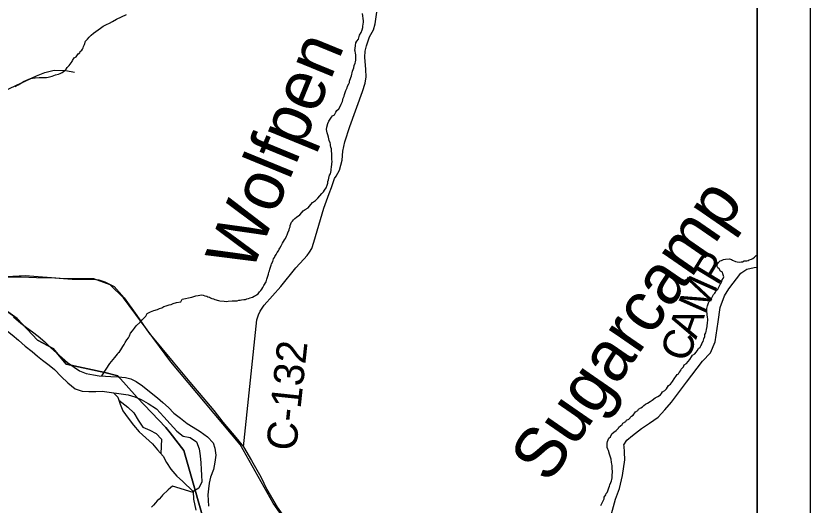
# Model space of a CAD drawing. Extents: x 44.2 to 78.2, y 4.5 to 26.5.
# Drawn here: x 51.74 to 53.236, y 19.485 to 20.407 of the extents above; entities that cross this region are included whole.
import ezdxf

# ---------------------------------------------------------------- set-up
doc = ezdxf.new("R2010")
doc.units = 0
for name, color, linetype in [('GM_X_County_Road', 7, 'Continuous'), ('GM_X_County_Road_Text', 7, 'Continuous'), ('GM_X_Major_River', 7, 'Continuous'), ('GM_X_Minor_River', 7, 'Continuous'), ('GM_X_Minor_River_Text', 7, 'Continuous'), ('GM_X_Rail_Line', 7, 'Continuous'), ('GM_X_Township_Road', 7, 'Continuous'), ('GM_X_Township_Road_Text', 7, 'Continuous'), ('GM_X_US_Route', 7, 'Continuous'), ('SH_Cut_Line', 7, 'Continuous'), ('SH_Data', 7, 'Continuous')]:
    doc.layers.add(name, color=color, linetype=linetype)

msp = doc.modelspace()

# ---------------------------------------------------------------- linework, layer by layer
at = {"layer": 'GM_X_County_Road'}
msp.add_lwpolyline([(52.1689, 19.5951), (52.1943, 19.834), (52.1973, 19.8438), (52.2001, 19.8505), (52.208, 19.8617), (52.2391, 19.8967), (52.2676, 19.9319), (52.2827, 19.9482), (52.2887, 19.9556), (52.2931, 19.9616), (52.2978, 19.9688), (52.3017, 19.9807), (52.32, 20.0445), (52.3251, 20.0581), (52.3305, 20.0721), (52.3349, 20.0834), (52.3406, 20.1002), (52.3434, 20.105), (52.3497, 20.1161), (52.3548, 20.1352), (52.3562, 20.1523), (52.3597, 20.1697), (52.3692, 20.1983), (52.3932, 20.2645), (52.3978, 20.2803), (52.3998, 20.2919), (52.3992, 20.3061), (52.3976, 20.329), (52.3982, 20.3404), (52.4007, 20.3506), (52.4064, 20.3671), (52.4136, 20.3809), (52.4171, 20.3916), (52.4198, 20.4137)], dxfattribs=at)
at = {"layer": 'GM_X_Major_River'}
for points in [[(51.6471, 19.8674), (51.6715, 19.8465), (51.6837, 19.8402), (51.695, 19.8327), (51.7082, 19.8261), (51.7213, 19.8156), (51.7336, 19.8059), (51.7451, 19.7958), (51.7582, 19.7846), (51.7713, 19.7745), (51.781, 19.766), (51.7907, 19.7582), (51.803, 19.7485), (51.8131, 19.7404), (51.8257, 19.7276), (51.8384, 19.7153), (51.8518, 19.7044), (51.8654, 19.6996), (51.8779, 19.6991), (51.8907, 19.6992), (51.9029, 19.6998)], [(51.7361, 19.8401), (51.7495, 19.8281), (51.7603, 19.8199), (51.7716, 19.8118), (51.7824, 19.8032), (51.7951, 19.7928), (51.8055, 19.7823), (51.8174, 19.7715), (51.8275, 19.7626), (51.8379, 19.7537), (51.8503, 19.7448), (51.8604, 19.7381), (51.8728, 19.733), (51.8864, 19.7305), (51.8973, 19.7288), (51.9094, 19.7279), (51.9193, 19.7277), (51.9329, 19.7267), (51.9469, 19.7258), (51.9567, 19.7233), (51.9672, 19.7178), (51.9788, 19.7097), (51.9949, 19.6965), (52.0068, 19.6872), (52.0173, 19.6786), (52.0277, 19.669), (52.0377, 19.6585), (52.0501, 19.6488), (52.0631, 19.6391), (52.074, 19.6317), (52.0871, 19.6239), (52.1013, 19.6138), (52.1117, 19.6022), (52.1149, 19.5927), (52.1166, 19.5789), (52.1152, 19.5657), (52.1123, 19.5524), (52.1068, 19.538), (52.1043, 19.5266), (52.103, 19.5156), (52.102, 19.5042), (52.1022, 19.4947), (52.1028, 19.4829)], [(51.9029, 19.6998), (51.9516, 19.693), (51.9644, 19.689), (51.9761, 19.6838), (51.9892, 19.6764), (52.0053, 19.6663), (52.0187, 19.6512), (52.0309, 19.6381), (52.0432, 19.6246), (52.0555, 19.6153), (52.0687, 19.6124), (52.0803, 19.6042), (52.0858, 19.5912), (52.0874, 19.5779), (52.0887, 19.5645), (52.0892, 19.552), (52.0898, 19.5413), (52.0903, 19.5288), (52.0852, 19.517), (52.0745, 19.5107), (52.0746, 19.4963), (52.0795, 19.4757)]]:
    msp.add_lwpolyline(points, dxfattribs=at)
at = {"layer": 'GM_X_Minor_River'}
for points in [[(51.7392, 20.2739), (51.745, 20.2772), (51.7511, 20.2808), (51.7558, 20.2837), (51.7592, 20.2852), (51.7646, 20.2877), (51.7677, 20.2887), (51.7715, 20.2898), (51.7768, 20.29), (51.7844, 20.291), (51.7947, 20.2907), (51.7981, 20.291), (51.8015, 20.2913), (51.8088, 20.2934), (51.8149, 20.2955), (51.8207, 20.2968), (51.8241, 20.2986), (51.8276, 20.3001), (51.8299, 20.3019), (51.8326, 20.3041), (51.835, 20.3067), (51.8373, 20.3097), (51.8405, 20.3134), (51.8448, 20.3186), (51.8467, 20.3208), (51.8472, 20.3231), (51.8503, 20.3276), (51.8538, 20.3297), (51.8577, 20.3353), (51.8608, 20.3375), (51.8616, 20.3398), (51.8647, 20.342), (51.8659, 20.3442), (51.8671, 20.3468), (51.8676, 20.3495), (51.8696, 20.3532), (51.8716, 20.3592), (51.8751, 20.3629), (51.8783, 20.367), (51.8822, 20.3707), (51.8868, 20.3744), (51.8911, 20.3773), (51.8953, 20.3806), (51.8996, 20.3836), (51.9046, 20.3872), (51.9112, 20.3905), (51.9166, 20.3934), (51.9223, 20.3966), (51.93, 20.4006), (51.9485, 20.4092)], [(52.3938, 20.3877), (52.3948, 20.3953), (52.3949, 20.3975), (52.3942, 20.4017), (52.3936, 20.4067), (52.3929, 20.4112)], [(52.2497, 19.9916), (52.2513, 19.9946), (52.2525, 19.9979), (52.255, 20.004), (52.2558, 20.007), (52.2566, 20.0096), (52.2571, 20.0119), (52.2595, 20.0179), (52.2611, 20.0201), (52.263, 20.0227), (52.2654, 20.0253), (52.2689, 20.0279), (52.275, 20.0319), (52.2786, 20.0363), (52.2813, 20.0397), (52.2852, 20.0422), (52.291, 20.0455), (52.2957, 20.0518), (52.2988, 20.0552), (52.3046, 20.0592), (52.3089, 20.0632), (52.3128, 20.0681), (52.3167, 20.0722), (52.3198, 20.0751), (52.3218, 20.0785), (52.3246, 20.0826), (52.3266, 20.0882), (52.3275, 20.092), (52.3279, 20.095), (52.3291, 20.098), (52.3296, 20.101), (52.3312, 20.1067), (52.3325, 20.1093), (52.3338, 20.1157), (52.3342, 20.1187), (52.3347, 20.1214), (52.3352, 20.1282), (52.3357, 20.1327), (52.3354, 20.1362), (52.3356, 20.1441), (52.3353, 20.1472), (52.3347, 20.1525), (52.3344, 20.1563), (52.3337, 20.1597), (52.333, 20.1624), (52.3327, 20.1651), (52.332, 20.1677), (52.3306, 20.1719), (52.3299, 20.175), (52.3289, 20.1784), (52.3279, 20.1826), (52.3264, 20.1865), (52.3258, 20.1895), (52.3255, 20.1926), (52.326, 20.1975), (52.3276, 20.2039), (52.3297, 20.2088), (52.332, 20.2121), (52.3348, 20.2162), (52.3368, 20.2185), (52.3402, 20.2206), (52.343, 20.2255), (52.345, 20.2285), (52.3485, 20.2318), (52.3513, 20.2363), (52.3529, 20.2408), (52.3553, 20.2453), (52.3561, 20.2487), (52.3566, 20.2517), (52.3586, 20.2554), (52.359, 20.2585), (52.3615, 20.2664), (52.3643, 20.2716), (52.3651, 20.2742), (52.3671, 20.2787), (52.3684, 20.2814), (52.3688, 20.2836), (52.3709, 20.2908), (52.3725, 20.2942), (52.3742, 20.3025), (52.3767, 20.3089), (52.3771, 20.3134), (52.3792, 20.3179), (52.38, 20.3205), (52.3804, 20.3235), (52.3806, 20.3308), (52.3803, 20.3334), (52.38, 20.3365), (52.379, 20.3403), (52.3786, 20.3426), (52.3791, 20.3452), (52.3796, 20.3513), (52.3805, 20.3562), (52.3825, 20.3595), (52.3853, 20.3633), (52.3869, 20.3678), (52.3877, 20.3704), (52.3905, 20.3753), (52.3922, 20.3809), (52.3938, 20.3847), (52.3938, 20.3877)], [(51.9021, 19.7284), (51.9173, 19.7518), (51.9267, 19.7633), (51.9318, 19.7696), (51.933, 19.7718), (51.9354, 19.7737), (51.9378, 19.7778), (51.9397, 19.7808), (51.9421, 19.7841), (51.9441, 19.7875), (51.9464, 19.7912), (51.9496, 19.7968), (51.9524, 19.8005), (51.9544, 19.8039), (51.9564, 19.8088), (51.9599, 19.8136), (51.9619, 19.8158), (51.9635, 19.8185), (51.9666, 19.8229), (51.9744, 19.8296), (51.9779, 19.834), (51.9853, 19.841), (51.9877, 19.8459), (51.9939, 19.8495), (52, 19.8517), (52.0073, 19.8534), (52.0111, 19.8555), (52.015, 19.8566), (52.0188, 19.8591), (52.0234, 19.8605), (52.0288, 19.8623), (52.0326, 19.8633), (52.0364, 19.8647), (52.0426, 19.8669), (52.0513, 19.8681), (52.0534, 19.873), (52.0717, 19.8767), (52.0793, 19.8792), (52.0839, 19.8802), (52.0866, 19.8809), (52.0896, 19.8812), (52.0931, 19.8807), (52.0964, 19.8795), (52.0998, 19.8786), (52.1021, 19.8778), (52.1047, 19.877), (52.107, 19.8758), (52.1096, 19.8746), (52.1122, 19.8738), (52.1152, 19.8722), (52.1217, 19.8705), (52.1247, 19.87), (52.1323, 19.8691), (52.1368, 19.8689), (52.1402, 19.8692), (52.1475, 19.8698), (52.1539, 19.87), (52.157, 19.8703), (52.16, 19.871), (52.1627, 19.8713), (52.165, 19.8716), (52.1699, 19.8722), (52.1726, 19.8726), (52.1753, 19.8736), (52.1784, 19.8743), (52.1818, 19.8757), (52.186, 19.8771), (52.1891, 19.879), (52.1914, 19.88), (52.1937, 19.8815), (52.1964, 19.8829), (52.1992, 19.8867), (52.2015, 19.8893), (52.2035, 19.8919), (52.2055, 19.8952), (52.2075, 19.8986), (52.2114, 19.9061), (52.2131, 19.9106), (52.2143, 19.9143), (52.216, 19.9204), (52.2168, 19.9238), (52.2177, 19.9264), (52.2185, 19.9298), (52.2197, 19.9335), (52.221, 19.9369), (52.2218, 19.9396), (52.2242, 19.9444), (52.225, 19.9467), (52.2254, 19.949), (52.2274, 19.9516), (52.2279, 19.9538), (52.2302, 19.9576), (52.2322, 19.9613), (52.2346, 19.9643), (52.2362, 19.9673), (52.2377, 19.9695), (52.2401, 19.9736), (52.2425, 19.9789), (52.2465, 19.9848), (52.2481, 19.9874), (52.2497, 19.9916)], [(52.9691, 19.7102), (52.973, 19.7128), (52.9746, 19.7157), (52.9769, 19.718), (52.9801, 19.7232), (52.9841, 19.7292), (52.9856, 19.7314), (52.9883, 19.7325), (52.9895, 19.7347), (52.9923, 19.7388), (52.9931, 19.7411), (52.9974, 19.7459), (52.9986, 19.7493), (53.0033, 19.7522), (53.006, 19.7555), (53.0091, 19.7596), (53.0127, 19.7645), (53.0143, 19.7674), (53.0185, 19.77), (53.0213, 19.7733), (53.0232, 19.7759), (53.026, 19.7804), (53.0287, 19.7826), (53.0299, 19.7849), (53.0315, 19.7871), (53.0327, 19.7909), (53.0343, 19.7931), (53.0359, 19.7984), (53.0376, 19.8025), (53.0377, 19.8067), (53.0393, 19.81), (53.0401, 19.8123), (53.0406, 19.8157), (53.0419, 19.8217), (53.0423, 19.8244), (53.0428, 19.8274), (53.043, 19.835), (53.0427, 19.8396), (53.042, 19.843), (53.0421, 19.8453), (53.0414, 19.8498), (53.0416, 19.8555), (53.042, 19.8582), (53.0425, 19.8604), (53.0433, 19.8627), (53.0445, 19.8664), (53.0457, 19.8687), (53.0484, 19.8713), (53.0504, 19.8746), (53.052, 19.878), (53.054, 19.8821), (53.0564, 19.8843), (53.0579, 19.8866), (53.0595, 19.8899), (53.0619, 19.8922), (53.0642, 19.8955), (53.0671, 19.9023), (53.0698, 19.9064), (53.0703, 19.9098), (53.0723, 19.912), (53.0731, 19.915), (53.0717, 19.9207), (53.0707, 19.9242), (53.0673, 19.9262), (53.0644, 19.93), (53.0618, 19.9324), (53.0607, 19.9347), (53.0608, 19.9385), (53.0635, 19.9422), (53.0666, 19.9452), (53.069, 19.9462), (53.0728, 19.9477), (53.0766, 19.9487), (53.0838, 19.9489), (53.0876, 19.9476), (53.0899, 19.9468), (53.0951, 19.9444), (53.0985, 19.9432), (53.1031, 19.9431), (53.1061, 19.9434), (53.1088, 19.9437), (53.1118, 19.9451), (53.1141, 19.9451), (53.1164, 19.9454), (53.1191, 19.9461), (53.1214, 19.9471), (53.1256, 19.9482), (53.1279, 19.95), (53.131, 19.9522), (53.1345, 19.9551), (53.1359, 19.9558)], [(52.8415, 19.4844), (52.843, 19.4866), (52.8459, 19.493), (52.8479, 19.4967), (52.8483, 19.5001), (52.8515, 19.5042), (52.8519, 19.5069), (52.8539, 19.5091), (52.8551, 19.5117), (52.8567, 19.5174), (52.8584, 19.5207), (52.8588, 19.5234), (52.8608, 19.5275), (52.862, 19.5309), (52.8625, 19.5332), (52.8629, 19.5366), (52.8634, 19.5407), (52.8636, 19.5479), (52.8634, 19.5544), (52.8631, 19.5589), (52.8625, 19.5627), (52.8621, 19.5654), (52.8615, 19.5715), (52.8601, 19.5757), (52.858, 19.5811), (52.8563, 19.5879), (52.8552, 19.5903), (52.8538, 19.5937), (52.8535, 19.599), (52.8536, 19.6017), (52.8544, 19.6047), (52.8569, 19.6111), (52.8603, 19.6136), (52.8628, 19.6193), (52.8663, 19.6226), (52.8709, 19.6255), (52.8748, 19.63), (52.876, 19.6322), (52.8818, 19.637), (52.8834, 19.6392), (52.8888, 19.6425), (52.8904, 19.6451), (52.8946, 19.6473), (52.8993, 19.6528), (52.9024, 19.6547), (52.9071, 19.6606), (52.9117, 19.6635), (52.9129, 19.6661), (52.9172, 19.6683), (52.9203, 19.6705), (52.9226, 19.6727), (52.9261, 19.6753), (52.9296, 19.6771), (52.9346, 19.6804), (52.9384, 19.6829), (52.9439, 19.6873), (52.9492, 19.6895), (52.9539, 19.6928), (52.9562, 19.6957), (52.9578, 19.6984), (52.9621, 19.7009), (52.9652, 19.7042), (52.9691, 19.7102)], [(51.924, 19.6968), (51.9326, 19.6887), (51.9365, 19.6753), (51.942, 19.6627), (51.9516, 19.6492), (51.9619, 19.6357), (51.9727, 19.6234), (51.985, 19.6118), (51.9977, 19.6006), (52.0069, 19.5894), (52.0177, 19.5774), (52.0243, 19.5652), (52.0324, 19.5529), (52.0432, 19.5398), (52.0544, 19.5301), (52.0745, 19.5107)], [(51.9343, 19.6829), (51.9512, 19.6698), (51.9627, 19.6589), (51.9704, 19.6451), (51.9793, 19.6317), (51.9928, 19.6261), (52.0048, 19.6202), (52.0145, 19.6091), (52.0133, 19.5824)], [(52.0745, 19.509), (52.0353, 19.5206), (52.0318, 19.5177), (52.0271, 19.514), (52.0162, 19.5037), (52.0143, 19.5011), (52.01, 19.4966), (52.0065, 19.4929), (52.0033, 19.4892), (51.9994, 19.4852), (51.9959, 19.4811)]]:
    msp.add_lwpolyline(points, dxfattribs=at)
at = {"layer": 'GM_X_Rail_Line'}
for points in [[(53.1359, 18.9756), (53.1359, 25.4014)], [(53.1359, 18.8803), (52.8787, 18.9518), (52.4529, 19.1732), (52.4355, 19.1892), (52.2249, 19.4887), (52.1626, 19.5993), (52.0324, 19.7548), (51.9429, 19.8757), (51.918, 19.9004), (51.8875, 19.9114), (51.8322, 19.9117), (51.7576, 19.9172), (51.6529, 19.9117)], [(51.7043, 19.8639), (51.7427, 19.8368), (51.7811, 19.7961), (51.8105, 19.7803), (51.8353, 19.7509), (51.9076, 19.7351), (51.9324, 19.7284), (51.9686, 19.6877), (52.0228, 19.6312), (52.0308, 19.6211), (52.0567, 19.5883), (52.1063, 19.4143)], [(52.1063, 19.4143), (52.0567, 19.5883), (52.0308, 19.6211), (52.0228, 19.6312), (51.9686, 19.6877), (51.9324, 19.7284), (51.9076, 19.7351), (51.8353, 19.7509), (51.8105, 19.7803), (51.7811, 19.7961), (51.7427, 19.8368), (51.7043, 19.8639)]]:
    msp.add_lwpolyline(points, dxfattribs=at)
at = {"layer": 'GM_X_Township_Road'}
for points in [[(51.3852, 20.0768), (51.3966, 20.0815), (51.4092, 20.0852), (51.4232, 20.0891), (51.4386, 20.0943), (51.4515, 20.1002), (51.4663, 20.1105), (51.4796, 20.1201), (51.4963, 20.1372), (51.5095, 20.1449), (51.5268, 20.1557), (51.5418, 20.1655), (51.5598, 20.1727), (51.576, 20.1795), (51.5991, 20.1911), (51.6257, 20.2149), (51.6425, 20.2251), (51.6701, 20.2428), (51.7791, 20.2941), (51.7952, 20.3005), (51.8123, 20.3043), (51.8346, 20.3038), (51.8508, 20.3011)], [(52.8855, 19.5964), (52.8854, 19.5984), (52.8909, 19.6072), (52.9015, 19.6161), (52.9181, 19.6294), (52.9335, 19.6392), (52.95, 19.6508), (52.9625, 19.6644), (52.975, 19.6789), (53.0029, 19.7165), (53.0334, 19.7562), (53.0485, 19.7721), (53.0571, 19.7925), (53.0628, 19.8306), (53.0668, 19.8576), (53.0745, 19.8791), (53.0829, 19.8923), (53.1054, 19.9224), (53.117, 19.9299), (53.1306, 19.9329), (53.1359, 19.9336)], [(52.6304, 19.0813), (52.6336, 19.0862), (52.6552, 19.1086), (52.7307, 19.1855), (52.7536, 19.2061), (52.783, 19.2436), (52.8004, 19.2699), (52.8199, 19.2941), (52.8353, 19.3196), (52.8358, 19.3203), (52.8498, 19.3476), (52.8557, 19.3693), (52.8525, 19.3988), (52.8491, 19.4228), (52.8695, 19.4965), (52.8768, 19.5163), (52.8829, 19.541), (52.8868, 19.5707), (52.8861, 19.5848), (52.8855, 19.5964)]]:
    msp.add_lwpolyline(points, dxfattribs=at)
at = {"layer": 'GM_X_US_Route'}
for points in [[(51.7255, 19.9152), (51.7501, 19.9154), (51.7793, 19.9142), (51.8137, 19.9133), (51.8466, 19.911), (51.8855, 19.911), (51.8969, 19.9097), (51.9079, 19.9059), (51.9153, 19.9023), (51.9252, 19.8967), (51.9446, 19.8758), (51.9681, 19.8421), (51.991, 19.8098), (52.0155, 19.7802), (52.0364, 19.7544), (52.0397, 19.7505)], [(52.0397, 19.7505), (52.068, 19.7167), (52.0922, 19.6876), (52.1129, 19.6632), (52.1302, 19.6415), (52.1513, 19.6165), (52.1689, 19.5951)], [(52.1689, 19.5951), (52.1843, 19.5689), (52.2016, 19.5381), (52.2128, 19.5146), (52.2321, 19.4812), (52.2495, 19.4575), (52.2541, 19.451)]]:
    msp.add_lwpolyline(points, dxfattribs=at)
at = {"layer": 'SH_Cut_Line'}
msp.add_lwpolyline([(48.642, 18.6014), (53.1359, 18.6014), (53.1359, 25.4014)], dxfattribs=at)
at = {"layer": 'SH_Data'}
for p, q in [((53.2359, 25.5014), (53.2359, 18.5014)), ((53.1359, 25.4014), (53.1359, 18.6014))]:
    msp.add_line(p, q, dxfattribs=at)

# ---------------------------------------------------------------- texts
at = {"layer": 'GM_X_County_Road_Text'}
msp.add_text('C-132', height=0.05682, rotation=83.9334, dxfattribs=at).set_placement((52.2679, 19.5858))
at = {"layer": 'GM_X_Minor_River_Text'}
for s, rotation, p in [('Wolfpen', 67.6865, (52.1831, 19.9198)), ('Sugarcamp', 55.343, (52.7437, 19.5234))]:
    msp.add_text(s, height=0.09471, rotation=rotation, dxfattribs=at).set_placement(p)
at = {"layer": 'GM_X_Township_Road_Text'}
for s, rotation, p in [('P', 58.7209, (53.0619, 19.8967)), ('M', 66.0393, (53.0377, 19.842)), ('A', 70.1492, (53.0211, 19.796)), ('C', 70.1863, (53.0053, 19.7521))]:
    msp.add_text(s, height=0.0568, rotation=rotation, dxfattribs=at).set_placement(p)

doc.saveas('drawing.dxf')
